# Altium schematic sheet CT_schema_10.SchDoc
size 281 x 153 mm
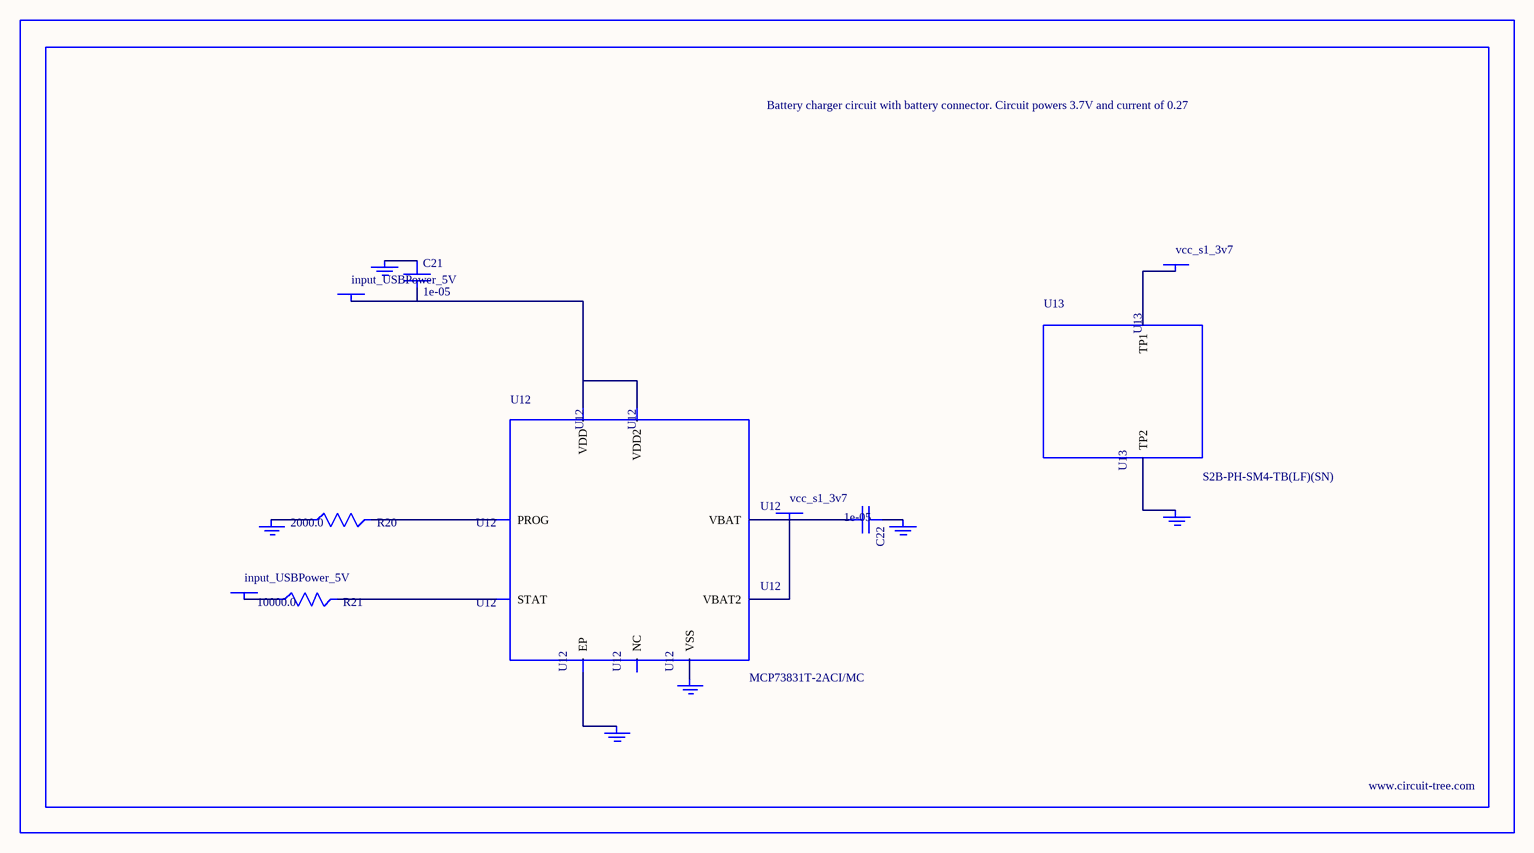
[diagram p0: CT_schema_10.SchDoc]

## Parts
BORDER9  (no value)
C21  1e-05  [C1206]
C22  1e-05  [C1206]
GND_INSTANCE_9_0  (no value)
GND_INSTANCE_9_1  (no value)
GND_INSTANCE_9_2  (no value)
GND_INSTANCE_9_3  (no value)
GND_INSTANCE_9_4  (no value)
GND_INSTANCE_9_5  (no value)
POWER_INSTANCE_9_0  input_USBPower_5V
POWER_INSTANCE_9_1  input_USBPower_5V
POWER_INSTANCE_9_2  vcc_s1_3v7
POWER_INSTANCE_9_3  vcc_s1_3v7
R20  2000.0  [R0603]
R21  10000.0  [R0603]
U12  MCP73831T-2ACI/MC  [DFN8_2X3MC]
U13  S2B-PH-SM4-TB(LF)(SN)  [JST-2-SMD]

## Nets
NetC21_1: C21.1 GND_INSTANCE_9_0.0(GND)
NetC21_2: C21.2 POWER_INSTANCE_9_0.0(PWR) U12.1(VDD) U12.2(VDD2)
NetC22_1: C22.1 GND_INSTANCE_9_1.0(GND)
NetC22_2: C22.2 POWER_INSTANCE_9_2.0(PWR) U12.3(VBAT) U12.4(VBAT2)
NetGND_INSTANCE_9_2_0: GND_INSTANCE_9_2.0(GND) R20.1
NetGND_INSTANCE_9_3_0: GND_INSTANCE_9_3.0(GND) U12.9(EP)
NetGND_INSTANCE_9_4_0: GND_INSTANCE_9_4.0(GND) U12.6(VSS)
NetGND_INSTANCE_9_5_0: GND_INSTANCE_9_5.0(GND) U13.2(TP2)
NetPOWER_INSTANCE_9_1_0: POWER_INSTANCE_9_1.0(PWR) R21.1
NetPOWER_INSTANCE_9_3_0: POWER_INSTANCE_9_3.0(PWR) U13.1(TP1)
NetR20_2: R20.2 U12.8(PROG)
NetR21_2: R21.2 U12.5(STAT)

Not connected (* = marked no-connect by the designer): U12 7(NC)

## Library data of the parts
BORDER9 = BORDER_PAGE9
C21 C22 = C1206C106K3RACTU
GND_INSTANCE_9_0-GND_INSTANCE_9_5 = GND
POWER_INSTANCE_9_0-POWER_INSTANCE_9_3 = PWR
R20 = RC0603JR-072KL
R21 = RC0603JR-0710KL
